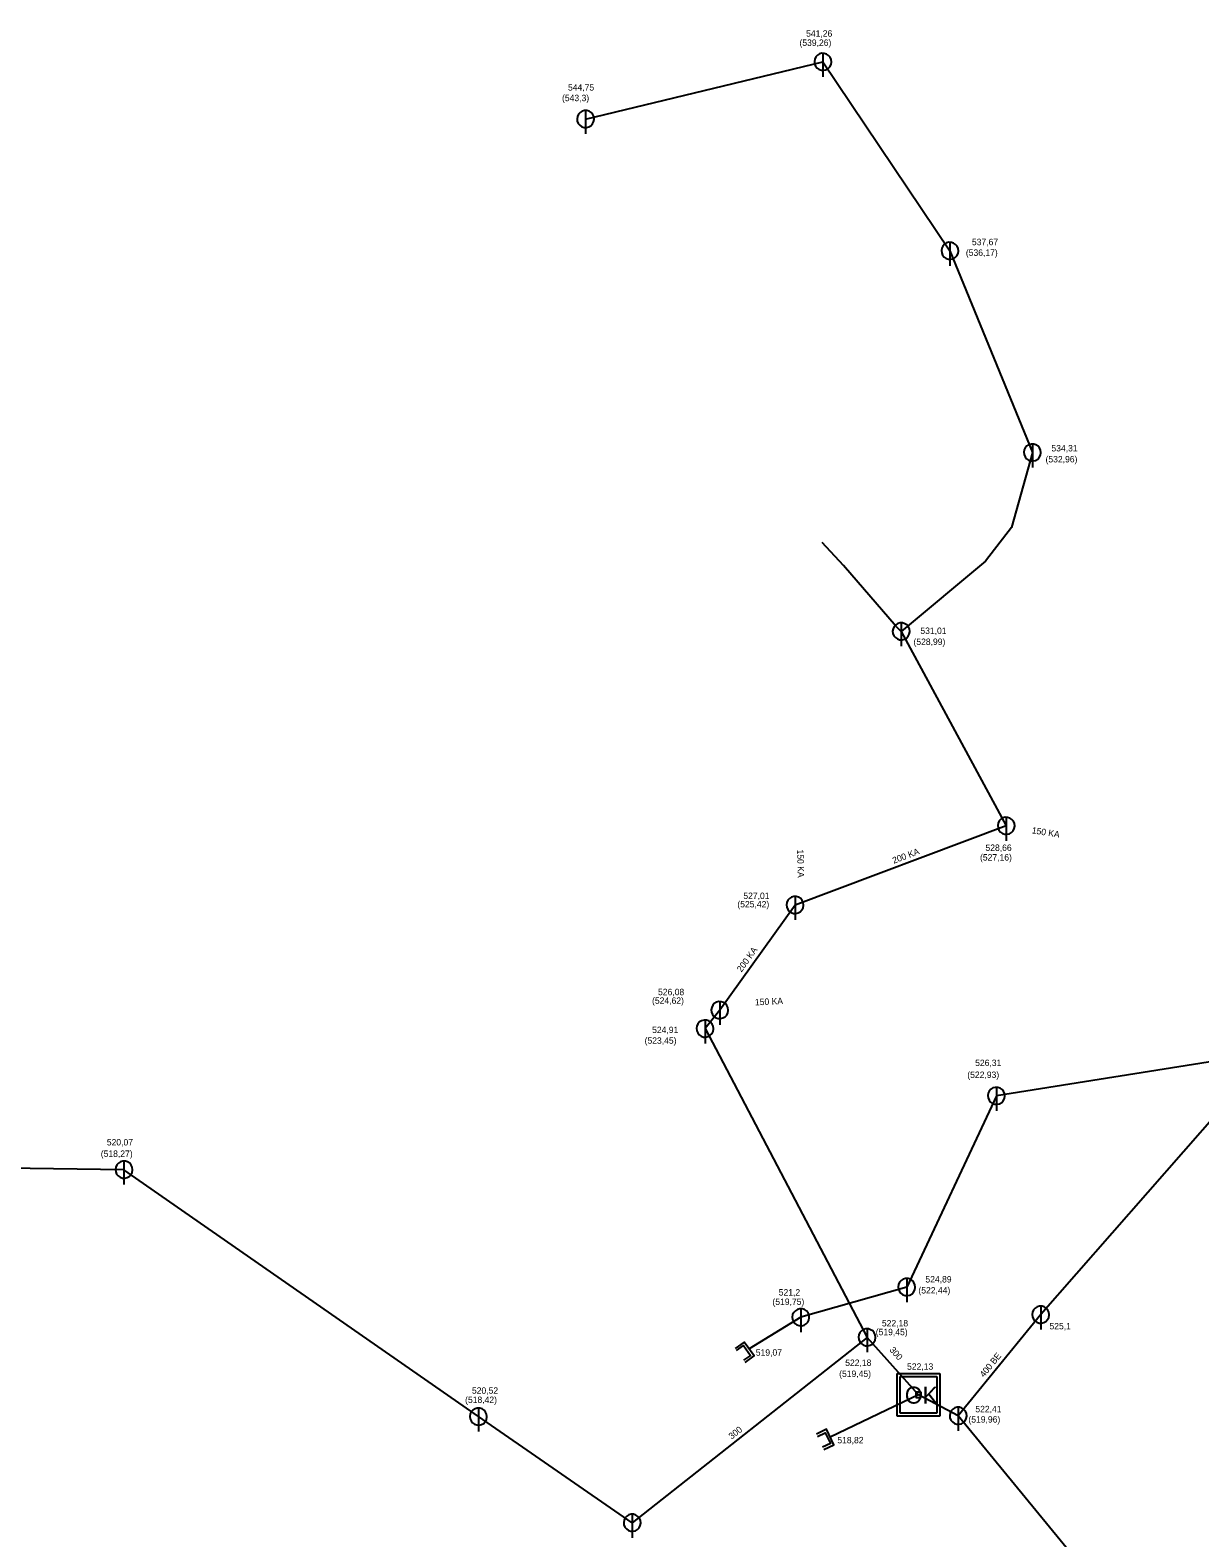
# Model space of a CAD drawing. Extents: x -476058 to -471893, y -1155786 to -1152000.
# Drawn here: x -473765.3 to -473628.2, y -1153927.9 to -1153751.2 of the extents above; entities that cross this region are included whole.
import ezdxf

# ---------------------------------------------------------------- set-up
doc = ezdxf.new("R2010")
doc.units = 0
for name, color, linetype in [('Vrstva 10', 7, 'Continuous'), ('Vrstva 13', 7, 'Continuous'), ('Vrstva 18', 7, 'Continuous'), ('Vrstva 19', 7, 'Continuous'), ('Vrstva 3', 7, 'Continuous'), ('Vrstva 35', 7, 'Continuous'), ('Vrstva 4', 7, 'Continuous'), ('Vrstva 45', 7, 'Continuous'), ('Vrstva 46', 7, 'Continuous'), ('Vrstva 50', 7, 'Continuous')]:
    doc.layers.add(name, color=color, linetype=linetype)

msp = doc.modelspace()

# ---------------------------------------------------------------- linework, layer by layer
at = {"layer": 'Vrstva 10'}
for p, q in [((-473672.36, -1153753.86), (-473672.36, -1153756.61)), ((-473700.18, -1153760.57), (-473700.18, -1153763.32)), ((-473657.47, -1153776.02), (-473657.47, -1153778.76)), ((-473647.81, -1153799.65), (-473647.81, -1153802.4)), ((-473663.19, -1153820.62), (-473663.19, -1153823.37)), ((-473650.88, -1153843.4), (-473650.88, -1153846.15)), ((-473675.63, -1153852.69), (-473675.63, -1153855.44)), ((-473684.45, -1153865), (-473684.45, -1153867.75)), ((-473686.18, -1153867.17), (-473686.18, -1153869.92)), ((-473652.03, -1153875.05), (-473652.03, -1153877.8)), ((-473754.28, -1153883.71), (-473754.28, -1153886.45)), ((-473662.54, -1153897.47), (-473662.54, -1153900.22)), ((-473646.84, -1153900.7), (-473646.84, -1153903.45)), ((-473674.96, -1153901), (-473674.96, -1153903.75)), ((-473667.19, -1153903.36), (-473667.19, -1153906.11)), ((-473663.66, -1153908.6), (-473658.66, -1153908.6)), ((-473663.66, -1153913.6), (-473663.66, -1153908.6)), ((-473663.31, -1153908.95), (-473659.01, -1153908.95)), ((-473663.31, -1153913.25), (-473663.31, -1153908.95)), ((-473659.01, -1153908.95), (-473659.01, -1153913.25)), ((-473658.66, -1153908.6), (-473658.66, -1153913.6)), ((-473712.74, -1153912.65), (-473712.74, -1153915.4)), ((-473656.5, -1153912.55), (-473656.5, -1153915.3)), ((-473658.66, -1153913.6), (-473663.66, -1153913.6)), ((-473659.01, -1153913.25), (-473663.31, -1153913.25)), ((-473694.71, -1153925.09), (-473694.71, -1153927.84))]:
    msp.add_line(p, q, dxfattribs=at)
for points in [[(-473671.36, -1153754.86), (-473671.4, -1153754.58), (-473671.51, -1153754.33), (-473671.7, -1153754.11), (-473671.93, -1153753.96), (-473672.2, -1153753.88), (-473672.48, -1153753.87), (-473672.76, -1153753.95), (-473673, -1153754.09), (-473673.19, -1153754.3), (-473673.31, -1153754.56), (-473673.36, -1153754.84), (-473673.33, -1153755.12), (-473673.22, -1153755.38), (-473673.04, -1153755.6), (-473672.81, -1153755.76), (-473672.54, -1153755.85), (-473672.26, -1153755.86), (-473671.98, -1153755.79), (-473671.74, -1153755.65), (-473671.54, -1153755.45), (-473671.41, -1153755.2), (-473671.36, -1153754.92), (-473671.36, -1153754.86)], [(-473699.18, -1153761.57), (-473699.22, -1153761.29), (-473699.34, -1153761.03), (-473699.52, -1153760.82), (-473699.75, -1153760.67), (-473700.02, -1153760.58), (-473700.31, -1153760.58), (-473700.58, -1153760.65), (-473700.82, -1153760.8), (-473701.01, -1153761.01), (-473701.13, -1153761.27), (-473701.18, -1153761.54), (-473701.15, -1153761.82), (-473701.04, -1153762.08), (-473700.86, -1153762.3), (-473700.63, -1153762.47), (-473700.36, -1153762.55), (-473700.08, -1153762.57), (-473699.8, -1153762.5), (-473699.56, -1153762.36), (-473699.37, -1153762.15), (-473699.24, -1153761.9), (-473699.18, -1153761.63), (-473699.18, -1153761.57)], [(-473656.47, -1153777.02), (-473656.51, -1153776.74), (-473656.62, -1153776.48), (-473656.81, -1153776.26), (-473657.04, -1153776.11), (-473657.31, -1153776.03), (-473657.6, -1153776.02), (-473657.87, -1153776.1), (-473658.11, -1153776.25), (-473658.3, -1153776.46), (-473658.42, -1153776.71), (-473658.47, -1153776.99), (-473658.44, -1153777.27), (-473658.33, -1153777.53), (-473658.15, -1153777.75), (-473657.92, -1153777.91), (-473657.65, -1153778), (-473657.37, -1153778.01), (-473657.1, -1153777.94), (-473656.85, -1153777.8), (-473656.66, -1153777.6), (-473656.53, -1153777.35), (-473656.47, -1153777.07), (-473656.47, -1153777.02)], [(-473646.81, -1153800.65), (-473646.85, -1153800.37), (-473646.97, -1153800.11), (-473647.15, -1153799.9), (-473647.39, -1153799.75), (-473647.66, -1153799.66), (-473647.94, -1153799.66), (-473648.21, -1153799.73), (-473648.45, -1153799.88), (-473648.64, -1153800.09), (-473648.76, -1153800.34), (-473648.81, -1153800.62), (-473648.78, -1153800.9), (-473648.67, -1153801.16), (-473648.49, -1153801.38), (-473648.26, -1153801.54), (-473647.99, -1153801.63), (-473647.71, -1153801.65), (-473647.44, -1153801.58), (-473647.19, -1153801.44), (-473647, -1153801.23), (-473646.87, -1153800.98), (-473646.81, -1153800.71), (-473646.81, -1153800.65)], [(-473662.19, -1153821.62), (-473662.23, -1153821.34), (-473662.35, -1153821.08), (-473662.53, -1153820.87), (-473662.77, -1153820.72), (-473663.04, -1153820.63), (-473663.32, -1153820.63), (-473663.59, -1153820.7), (-473663.83, -1153820.85), (-473664.02, -1153821.06), (-473664.14, -1153821.31), (-473664.19, -1153821.59), (-473664.16, -1153821.87), (-473664.05, -1153822.13), (-473663.87, -1153822.35), (-473663.64, -1153822.51), (-473663.37, -1153822.6), (-473663.09, -1153822.62), (-473662.82, -1153822.55), (-473662.57, -1153822.41), (-473662.38, -1153822.2), (-473662.25, -1153821.95), (-473662.19, -1153821.68), (-473662.19, -1153821.62)], [(-473649.88, -1153844.4), (-473649.92, -1153844.12), (-473650.03, -1153843.87), (-473650.22, -1153843.65), (-473650.45, -1153843.5), (-473650.72, -1153843.42), (-473651, -1153843.41), (-473651.28, -1153843.49), (-473651.52, -1153843.63), (-473651.71, -1153843.84), (-473651.83, -1153844.1), (-473651.88, -1153844.38), (-473651.84, -1153844.66), (-473651.73, -1153844.92), (-473651.56, -1153845.14), (-473651.33, -1153845.3), (-473651.06, -1153845.39), (-473650.78, -1153845.4), (-473650.5, -1153845.33), (-473650.26, -1153845.19), (-473650.06, -1153844.99), (-473649.93, -1153844.74), (-473649.88, -1153844.46), (-473649.88, -1153844.4)], [(-473674.63, -1153853.69), (-473674.67, -1153853.41), (-473674.79, -1153853.15), (-473674.97, -1153852.94), (-473675.21, -1153852.78), (-473675.48, -1153852.7), (-473675.76, -1153852.7), (-473676.03, -1153852.77), (-473676.27, -1153852.92), (-473676.46, -1153853.13), (-473676.58, -1153853.38), (-473676.63, -1153853.66), (-473676.6, -1153853.94), (-473676.49, -1153854.2), (-473676.31, -1153854.42), (-473676.08, -1153854.58), (-473675.81, -1153854.67), (-473675.53, -1153854.69), (-473675.26, -1153854.62), (-473675.01, -1153854.48), (-473674.82, -1153854.27), (-473674.69, -1153854.02), (-473674.63, -1153853.75), (-473674.63, -1153853.69)], [(-473683.45, -1153866), (-473683.49, -1153865.72), (-473683.61, -1153865.47), (-473683.79, -1153865.25), (-473684.03, -1153865.1), (-473684.3, -1153865.02), (-473684.58, -1153865.01), (-473684.85, -1153865.09), (-473685.09, -1153865.23), (-473685.28, -1153865.44), (-473685.4, -1153865.7), (-473685.45, -1153865.98), (-473685.42, -1153866.26), (-473685.31, -1153866.52), (-473685.13, -1153866.74), (-473684.9, -1153866.9), (-473684.63, -1153866.99), (-473684.35, -1153867), (-473684.08, -1153866.93), (-473683.83, -1153866.79), (-473683.64, -1153866.59), (-473683.51, -1153866.34), (-473683.45, -1153866.06), (-473683.45, -1153866)], [(-473685.18, -1153868.17), (-473685.22, -1153867.89), (-473685.33, -1153867.64), (-473685.52, -1153867.42), (-473685.75, -1153867.27), (-473686.02, -1153867.18), (-473686.3, -1153867.18), (-473686.58, -1153867.26), (-473686.82, -1153867.4), (-473687.01, -1153867.61), (-473687.13, -1153867.87), (-473687.18, -1153868.14), (-473687.15, -1153868.43), (-473687.04, -1153868.69), (-473686.86, -1153868.9), (-473686.63, -1153869.07), (-473686.36, -1153869.16), (-473686.08, -1153869.17), (-473685.8, -1153869.1), (-473685.56, -1153868.96), (-473685.36, -1153868.76), (-473685.23, -1153868.51), (-473685.18, -1153868.23), (-473685.18, -1153868.17)], [(-473651.03, -1153876.05), (-473651.07, -1153875.77), (-473651.19, -1153875.51), (-473651.37, -1153875.3), (-473651.6, -1153875.15), (-473651.88, -1153875.06), (-473652.16, -1153875.06), (-473652.43, -1153875.13), (-473652.67, -1153875.28), (-473652.86, -1153875.49), (-473652.98, -1153875.74), (-473653.03, -1153876.02), (-473653, -1153876.3), (-473652.89, -1153876.56), (-473652.71, -1153876.78), (-473652.48, -1153876.94), (-473652.21, -1153877.03), (-473651.93, -1153877.05), (-473651.66, -1153876.98), (-473651.41, -1153876.84), (-473651.22, -1153876.63), (-473651.09, -1153876.38), (-473651.03, -1153876.11), (-473651.03, -1153876.05)], [(-473753.28, -1153884.71), (-473753.32, -1153884.43), (-473753.43, -1153884.17), (-473753.61, -1153883.96), (-473753.85, -1153883.8), (-473754.12, -1153883.72), (-473754.4, -1153883.71), (-473754.67, -1153883.79), (-473754.92, -1153883.94), (-473755.1, -1153884.15), (-473755.23, -1153884.4), (-473755.28, -1153884.68), (-473755.24, -1153884.96), (-473755.14, -1153885.22), (-473754.96, -1153885.44), (-473754.73, -1153885.6), (-473754.46, -1153885.69), (-473754.18, -1153885.7), (-473753.9, -1153885.63), (-473753.66, -1153885.49), (-473753.46, -1153885.29), (-473753.33, -1153885.04), (-473753.28, -1153884.76), (-473753.28, -1153884.71)], [(-473661.54, -1153898.47), (-473661.58, -1153898.19), (-473661.7, -1153897.93), (-473661.88, -1153897.72), (-473662.11, -1153897.56), (-473662.39, -1153897.48), (-473662.67, -1153897.48), (-473662.94, -1153897.55), (-473663.18, -1153897.7), (-473663.37, -1153897.91), (-473663.49, -1153898.16), (-473663.54, -1153898.44), (-473663.51, -1153898.72), (-473663.4, -1153898.98), (-473663.22, -1153899.2), (-473662.99, -1153899.36), (-473662.72, -1153899.45), (-473662.44, -1153899.47), (-473662.17, -1153899.4), (-473661.92, -1153899.26), (-473661.73, -1153899.05), (-473661.6, -1153898.8), (-473661.54, -1153898.53), (-473661.54, -1153898.47)], [(-473645.84, -1153901.7), (-473645.88, -1153901.42), (-473646, -1153901.16), (-473646.18, -1153900.95), (-473646.42, -1153900.79), (-473646.68, -1153900.71), (-473646.97, -1153900.71), (-473647.24, -1153900.78), (-473647.48, -1153900.93), (-473647.67, -1153901.14), (-473647.79, -1153901.39), (-473647.84, -1153901.67), (-473647.81, -1153901.95), (-473647.7, -1153902.21), (-473647.52, -1153902.43), (-473647.29, -1153902.59), (-473647.02, -1153902.68), (-473646.74, -1153902.7), (-473646.47, -1153902.63), (-473646.22, -1153902.49), (-473646.03, -1153902.28), (-473645.9, -1153902.03), (-473645.84, -1153901.76), (-473645.84, -1153901.7)], [(-473673.96, -1153902), (-473673.99, -1153901.73), (-473674.11, -1153901.47), (-473674.29, -1153901.25), (-473674.53, -1153901.1), (-473674.8, -1153901.02), (-473675.08, -1153901.01), (-473675.35, -1153901.09), (-473675.59, -1153901.24), (-473675.78, -1153901.44), (-473675.91, -1153901.7), (-473675.96, -1153901.98), (-473675.92, -1153902.26), (-473675.81, -1153902.52), (-473675.64, -1153902.74), (-473675.41, -1153902.9), (-473675.14, -1153902.99), (-473674.85, -1153903), (-473674.58, -1153902.93), (-473674.34, -1153902.79), (-473674.14, -1153902.59), (-473674.01, -1153902.34), (-473673.96, -1153902.06), (-473673.96, -1153902)], [(-473666.19, -1153904.36), (-473666.23, -1153904.08), (-473666.35, -1153903.82), (-473666.53, -1153903.61), (-473666.77, -1153903.46), (-473667.04, -1153903.37), (-473667.32, -1153903.37), (-473667.59, -1153903.44), (-473667.83, -1153903.59), (-473668.02, -1153903.8), (-473668.14, -1153904.05), (-473668.19, -1153904.33), (-473668.16, -1153904.61), (-473668.05, -1153904.87), (-473667.87, -1153905.09), (-473667.64, -1153905.25), (-473667.37, -1153905.34), (-473667.09, -1153905.36), (-473666.82, -1153905.29), (-473666.57, -1153905.15), (-473666.38, -1153904.94), (-473666.25, -1153904.69), (-473666.19, -1153904.42), (-473666.19, -1153904.36)], [(-473681.48, -1153907.29), (-473680.43, -1153906.53), (-473681.6, -1153904.91), (-473682.65, -1153905.67)], [(-473682.48, -1153905.92), (-473681.67, -1153905.33), (-473680.85, -1153906.47), (-473681.66, -1153907.05)], [(-473711.74, -1153913.65), (-473711.78, -1153913.37), (-473711.9, -1153913.11), (-473712.08, -1153912.9), (-473712.31, -1153912.74), (-473712.58, -1153912.66), (-473712.87, -1153912.66), (-473713.14, -1153912.73), (-473713.38, -1153912.88), (-473713.57, -1153913.09), (-473713.69, -1153913.34), (-473713.74, -1153913.62), (-473713.71, -1153913.9), (-473713.6, -1153914.16), (-473713.42, -1153914.38), (-473713.19, -1153914.54), (-473712.92, -1153914.63), (-473712.64, -1153914.65), (-473712.36, -1153914.58), (-473712.12, -1153914.44), (-473711.93, -1153914.23), (-473711.8, -1153913.98), (-473711.74, -1153913.71), (-473711.74, -1153913.65)], [(-473655.5, -1153913.55), (-473655.54, -1153913.27), (-473655.66, -1153913.01), (-473655.84, -1153912.8), (-473656.08, -1153912.65), (-473656.35, -1153912.56), (-473656.63, -1153912.56), (-473656.9, -1153912.63), (-473657.14, -1153912.78), (-473657.33, -1153912.99), (-473657.45, -1153913.24), (-473657.5, -1153913.52), (-473657.47, -1153913.8), (-473657.36, -1153914.06), (-473657.18, -1153914.28), (-473656.95, -1153914.44), (-473656.68, -1153914.53), (-473656.4, -1153914.55), (-473656.13, -1153914.48), (-473655.88, -1153914.34), (-473655.69, -1153914.13), (-473655.56, -1153913.88), (-473655.5, -1153913.61), (-473655.5, -1153913.55)], [(-473672.27, -1153917.5), (-473671.09, -1153916.95), (-473671.95, -1153915.14), (-473673.13, -1153915.7)], [(-473673, -1153915.97), (-473672.1, -1153915.54), (-473671.49, -1153916.8), (-473672.4, -1153917.23)], [(-473693.71, -1153926.09), (-473693.75, -1153925.81), (-473693.87, -1153925.55), (-473694.05, -1153925.34), (-473694.29, -1153925.19), (-473694.55, -1153925.1), (-473694.84, -1153925.1), (-473695.11, -1153925.17), (-473695.35, -1153925.32), (-473695.54, -1153925.53), (-473695.66, -1153925.78), (-473695.71, -1153926.06), (-473695.68, -1153926.34), (-473695.57, -1153926.6), (-473695.39, -1153926.82), (-473695.16, -1153926.98), (-473694.89, -1153927.07), (-473694.61, -1153927.09), (-473694.34, -1153927.02), (-473694.09, -1153926.88), (-473693.9, -1153926.67), (-473693.77, -1153926.42), (-473693.71, -1153926.15), (-473693.71, -1153926.09)]]:
    msp.add_lwpolyline(points, dxfattribs=at)
at = {"layer": 'Vrstva 13'}
for p, q in [((-473660.86, -1153910.8), (-473661.46, -1153910.8)), ((-473661.46, -1153910.8), (-473661.46, -1153911.4)), ((-473660.86, -1153911.4), (-473660.86, -1153910.8)), ((-473661.46, -1153911.4), (-473660.86, -1153911.4))]:
    msp.add_line(p, q, dxfattribs=at)
at = {"layer": 'Vrstva 35'}
for points in [[(-473623.76, -1153871.56), (-473652.03, -1153876.05)], [(-473652.03, -1153876.05), (-473662.54, -1153898.47)], [(-473662.54, -1153898.47), (-473674.96, -1153902)], [(-473674.96, -1153902), (-473681.01, -1153905.72)]]:
    msp.add_lwpolyline(points, dxfattribs=at)
at = {"layer": 'Vrstva 45'}
for p, q in [((-473647.81, -1153800.65), (-473650.27, -1153809.43)), ((-473650.27, -1153809.43), (-473653.31, -1153813.41)), ((-473653.31, -1153813.41), (-473663.19, -1153821.62))]:
    msp.add_line(p, q, dxfattribs=at)
for points in [[(-473700.18, -1153761.57), (-473672.36, -1153754.86)], [(-473672.36, -1153754.86), (-473657.47, -1153777.02)], [(-473657.47, -1153777.02), (-473647.81, -1153800.65)], [(-473663.19, -1153821.62), (-473650.88, -1153844.4)], [(-473650.88, -1153844.4), (-473675.63, -1153853.69)], [(-473621.75, -1153873.09), (-473646.84, -1153901.7)], [(-473754.28, -1153884.71), (-473784.49, -1153884.3)], [(-473712.74, -1153913.65), (-473754.28, -1153884.71)], [(-473646.84, -1153901.7), (-473656.5, -1153913.55)], [(-473667.19, -1153904.36), (-473694.71, -1153926.09)], [(-473661.16, -1153911.1), (-473667.19, -1153904.36)], [(-473661.16, -1153911.1), (-473671.52, -1153916.04)], [(-473656.5, -1153913.55), (-473661.16, -1153911.1)], [(-473694.71, -1153926.09), (-473712.74, -1153913.65)], [(-473630.11, -1153945.73), (-473656.5, -1153913.55)]]:
    msp.add_lwpolyline(points, dxfattribs=at)
at = {"layer": 'Vrstva 46'}
for points in [[(-473675.63, -1153853.69), (-473684.45, -1153866)], [(-473684.45, -1153866), (-473686.18, -1153868.17)], [(-473686.18, -1153868.17), (-473667.19, -1153904.36)]]:
    msp.add_lwpolyline(points, dxfattribs=at)
at = {"layer": 'Vrstva 50'}
for points in [[(-473663.78, -1153821.03), (-473669.96, -1153813.89), (-473672.46, -1153811.22)], [(-473663.78, -1153821.03), (-473663.19, -1153821.62)]]:
    msp.add_lwpolyline(points, dxfattribs=at)

# ---------------------------------------------------------------- texts
at = {"layer": 'Vrstva 10'}
msp.add_text('OK', height=2, dxfattribs=at).set_placement((-473662.76, -1153912.13))
at = {"layer": 'Vrstva 18'}
for s, rotation, p in [('200 KA', 20.5647, (-473664.06, -1153848.86)), ('200 KA', 54.3823, (-473681.91, -1153861.62)), ('300 ', 311.8177, (-473664.62, -1153905.87)), ('400 BE', 50.8134, (-473653.48, -1153909.1)), ('300 ', 38.2949, (-473683.05, -1153916.35))]:
    msp.add_text(s, height=0.75, rotation=rotation, dxfattribs=at).set_placement(p)
at = {"layer": 'Vrstva 19'}
for rotation, p in [(350.9097, (-473647.92, -1153845.28)), (271.4387, (-473675.39, -1153847.2)), (2.876, (-473680.31, -1153865.46))]:
    msp.add_text('150 KA', height=0.75, rotation=rotation, dxfattribs=at).set_placement(p)
at = {"layer": 'Vrstva 3'}
for s, p in [('541,26', (-473674.33, -1153751.92)), ('544,75', (-473702.24, -1153758.24)), ('537,67', (-473654.9, -1153776.36)), ('534,31', (-473645.58, -1153800.53)), ('531,01', (-473660.94, -1153821.92)), ('528,66', (-473653.31, -1153847.35)), ('527,01', (-473681.69, -1153852.98)), ('526,08', (-473691.69, -1153864.26)), ('524,91', (-473692.38, -1153868.7)), ('526,31', (-473654.52, -1153872.56)), ('520,07', (-473756.29, -1153881.87)), ('524,89', (-473660.35, -1153897.93)), ('521,2', (-473677.54, -1153899.46)), ('522,18', (-473665.45, -1153903.08)), ('525,1', (-473645.81, -1153903.42)), ('519,07', (-473680.23, -1153906.51)), ('522,18', (-473669.75, -1153907.71)), ('522,13', (-473662.5, -1153908.16)), ('520,52', (-473713.5, -1153910.97)), ('522,41', (-473654.5, -1153913.14)), ('518,82', (-473670.67, -1153916.78))]:
    msp.add_text(s, height=0.75, dxfattribs=at).set_placement(p)
at = {"layer": 'Vrstva 4'}
for s, p in [('(539,26)', (-473675.11, -1153753)), ('(543,3)', (-473702.94, -1153759.48)), ('(536,17)', (-473655.61, -1153777.61)), ('(532,96)', (-473646.27, -1153801.82)), ('(528,99)', (-473661.75, -1153823.21)), ('(527,16)', (-473653.95, -1153848.48)), ('(525,42)', (-473682.39, -1153853.97)), ('(524,62)', (-473692.39, -1153865.27)), ('(523,45)', (-473693.26, -1153869.95)), ('(522,93)', (-473655.44, -1153873.96)), ('(518,27)', (-473757, -1153883.21)), ('(522,44)', (-473661.17, -1153899.22)), ('(519,75)', (-473678.28, -1153900.56)), ('(519,45)', (-473666.17, -1153904.11)), ('(519,45)', (-473670.46, -1153909)), ('(518,42)', (-473714.3, -1153912.05)), ('(519,96)', (-473655.31, -1153914.35))]:
    msp.add_text(s, height=0.75, dxfattribs=at).set_placement(p)

doc.saveas('drawing.dxf')
